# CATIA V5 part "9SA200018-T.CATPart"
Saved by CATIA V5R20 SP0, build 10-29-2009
Part number: 9SA200018-T
Revision: ANY
Definition: UNKNOWN
Nomenclature: 9SA200018-T
Source: Unknown
Bounding box of the stored display mesh (mm): x -7.312 to 7.312, y 0 to 5.95, z -7.5 to 7.5
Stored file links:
  C:\Users\Utente\Desktop\IO LAVORO\3D X SITO CF\CUMSA\3D files SA\SA 200518\9SA200018-T.CATPart
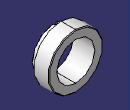
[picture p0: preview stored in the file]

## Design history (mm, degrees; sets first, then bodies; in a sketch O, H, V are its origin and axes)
Body1 "Chaflán1" (main body)
  Solid1: solid without history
